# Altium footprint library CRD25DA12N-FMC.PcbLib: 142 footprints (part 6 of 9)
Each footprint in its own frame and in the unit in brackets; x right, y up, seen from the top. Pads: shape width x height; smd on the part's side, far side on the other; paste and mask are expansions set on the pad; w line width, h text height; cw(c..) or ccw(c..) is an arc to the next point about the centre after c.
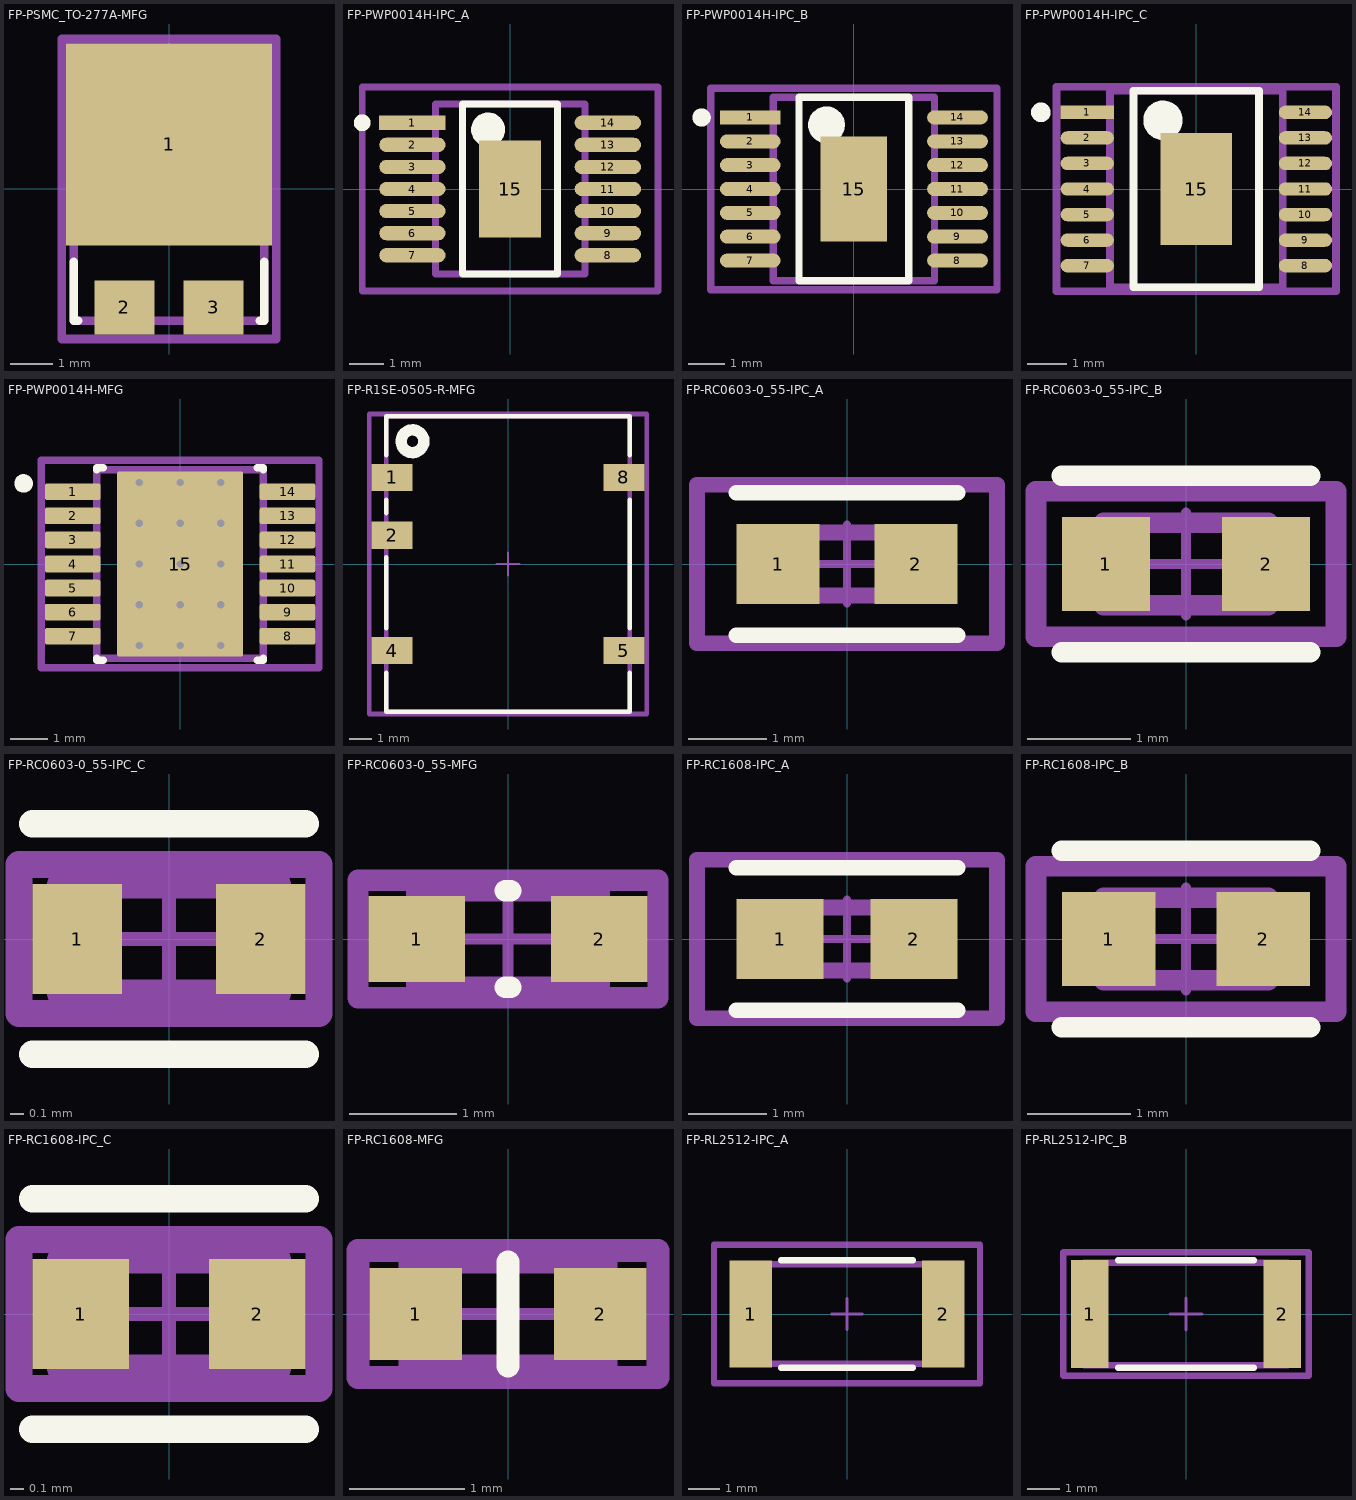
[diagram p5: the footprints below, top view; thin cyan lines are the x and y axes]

## FP-PSMC_TO-277A-MFG [mm]
pads (3):
  rect 4.8x4.72 smd paste+0 mask+0: 1(0,1.04)
  rect 1.4x1.27 smd paste+0 mask+0: 2(-1.04,-2.765) 3(1.04,-2.765)
Top Overlay:
  lines w0.2: -2.225,-1.695 -2.225,-3.075 -2.115,-3.075 ; 2.115,-3.075 2.225,-3.075 2.225,-1.695
Mechanical 5:
  lines w0.2: -2.5,-3.5 -2.5,3.5 2.5,3.5 2.5,-3.5 -2.5,-3.5
  text ".Designator" at 0,0 h1
Mechanical 13:
  lines w0.2: -2.225,-3.075 -2.225,3.075 2.225,3.075 2.225,-3.075 -2.225,-3.075
Mechanical 15:
  lines w0.2: -2.5,-3.5 -2.5,3.5 2.5,3.5 2.5,-3.5 -2.5,-3.5
Mechanical 16:
  lines w0.1: -0.5,0 0.5,0 ; 0,-0.5 0,0.5
3D body "Diode_STMicroelectronics_STPS1045SF_eec.STEP": height 0.25, standoff 0, extent -2.5,-3.5 2.5,3.5

## FP-PWP0014H-IPC_A [mm]
pads (15):
  rect 1.955x0.421 smd paste+0 mask+0: 1(-2.875,1.95)
  rrect100% 1.955x0.421 smd paste+0 mask+0: 2(-2.875,1.3) 3(-2.875,0.65) 4(-2.875,0) 5(-2.875,-0.65) 6(-2.875,-1.3) 7(-2.875,-1.95) 8(2.875,-1.95) 9(2.875,-1.3) 10(2.875,-0.65) 11(2.875,0) 12(2.875,0.65) 13(2.875,1.3) 14(2.875,1.95)
  rect 1.82x2.86 smd paste-1000 mask+0: 15(0,0)
Top Overlay:
  circle w0.25: c-4.353,1.95 r0.125
  circle w0.5: c-0.648,1.75 r0.25
  lines w0.2: -1.398,-2.5 -1.398,2.5 1.398,2.5 1.398,-2.5 -1.398,-2.5
Top Paste:
  rectangle: -0.507,-1.027 0.507,1.027
Mechanical 5:
  lines w0.2: -4.353,-3 -4.353,3 4.353,3 4.353,-3 -4.353,-3
  text ".Designator" at 0,0.188 h1
Mechanical 13:
  lines w0.2: -2.2,-2.5 -2.2,2.5 2.2,2.5 2.2,-2.5 -2.2,-2.5
Mechanical 15:
  lines w0.2: -4.353,-3 -4.353,3 4.353,3 4.353,-3 -4.353,-3
Mechanical 16:
  lines w0.1: -0.5,0 0.5,0 ; 0,-0.5 0,0.5
3D body "IC_Texas_Instruments_ALM2402FQPWPRQ1_eec.STEP": height 0.25, standoff 0, extent -4.353,-3 4.353,3

## FP-PWP0014H-IPC_B [mm]
pads (15):
  rect 1.655x0.381 smd paste+0 mask+0: 1(-2.825,1.95)
  rrect100% 1.655x0.381 smd paste+0 mask+0: 2(-2.825,1.3) 3(-2.825,0.65) 4(-2.825,0) 5(-2.825,-0.65) 6(-2.825,-1.3) 7(-2.825,-1.95) 8(2.825,-1.95) 9(2.825,-1.3) 10(2.825,-0.65) 11(2.825,0) 12(2.825,0.65) 13(2.825,1.3) 14(2.825,1.95)
  rect 1.82x2.86 smd paste-1000 mask+0: 15(0,0)
Top Overlay:
  circle w0.5: c-0.748,1.75 r0.25
  circle w0.25: c-4.153,1.95 r0.125
  lines w0.2: -1.498,-2.5 1.498,-2.5 1.498,2.5 -1.498,2.5 -1.498,-2.5
Top Paste:
  rectangle: -0.507,-1.027 0.507,1.027
Mechanical 5:
  lines w0.2: -3.903,-2.75 3.903,-2.75 3.903,2.75 -3.903,2.75 -3.903,-2.75
  text ".Designator" at 0,0.188 h1
Mechanical 13:
  lines w0.2: -2.2,-2.5 2.2,-2.5 2.2,2.5 -2.2,2.5 -2.2,-2.5
Mechanical 15:
  lines w0.2: -3.903,-2.75 3.903,-2.75 3.903,2.75 -3.903,2.75 -3.903,-2.75
Mechanical 16:
  lines w0.1: -0.5,0 0.5,0 ; 0,-0.5 0,0.5
3D body "IC_Texas_Instruments_ALM2402FQPWPRQ1_eec.STEP": height 0.25, standoff 0, extent -3.903,-2.75 3.903,2.75

## FP-PWP0014H-IPC_C [mm]
pads (15):
  rect 1.355x0.341 smd paste+0 mask+0: 1(-2.775,1.95)
  rrect100% 1.355x0.341 smd paste+0 mask+0: 2(-2.775,1.3) 3(-2.775,0.65) 4(-2.775,0) 5(-2.775,-0.65) 6(-2.775,-1.3) 7(-2.775,-1.95) 8(2.775,-1.95) 9(2.775,-1.3) 10(2.775,-0.65) 11(2.775,0) 12(2.775,0.65) 13(2.775,1.3) 14(2.775,1.95)
  rect 1.82x2.86 smd paste-1000 mask+0: 15(0,0)
Top Overlay:
  circle w0.5: c-0.848,1.75 r0.25
  circle w0.25: c-3.953,1.95 r0.125
  lines w0.2: -1.598,-2.5 1.598,-2.5 1.598,2.5 -1.598,2.5 -1.598,-2.5
Top Paste:
  rectangle: -0.507,-1.027 0.507,1.027
Mechanical 5:
  lines w0.2: -3.553,-2.6 3.553,-2.6 3.553,2.6 -3.553,2.6 -3.553,-2.6
  text ".Designator" at 0,0.188 h1
Mechanical 13:
  lines w0.2: -2.2,-2.5 2.2,-2.5 2.2,2.5 -2.2,2.5 -2.2,-2.5
Mechanical 15:
  lines w0.2: -3.553,-2.6 3.553,-2.6 3.553,2.6 -3.553,2.6 -3.553,-2.6
Mechanical 16:
  lines w0.1: -0.5,0 0.5,0 ; 0,-0.5 0,0.5
3D body "IC_Texas_Instruments_ALM2402FQPWPRQ1_eec.STEP": height 0.25, standoff 0, extent -3.553,-2.6 3.553,2.6

## FP-PWP0014H-MFG [mm]
pads (15):
  rrect22% 1.5x0.45 smd paste+0 mask+0: 1(-2.9,1.95) 2(-2.9,1.3) 3(-2.9,0.65) 4(-2.9,0) 5(-2.9,-0.65) 6(-2.9,-1.3) 7(-2.9,-1.95) 8(2.9,-1.95) 9(2.9,-1.3) 10(2.9,-0.65) 11(2.9,0) 12(2.9,0.65) 13(2.9,1.3) 14(2.9,1.95)
  rrect3% 3.4x5 smd paste-1000 mask-1000: 15(0,0)
via 1.1,2.2 diameter 0.5 hole 0.2
via 1.1,1.1 diameter 0.5 hole 0.2
via 1.1,0 diameter 0.5 hole 0.2
via 1.1,-1.1 diameter 0.5 hole 0.2
via 1.1,-2.2 diameter 0.5 hole 0.2
via -1.1,2.2 diameter 0.5 hole 0.2
via -1.1,1.1 diameter 0.5 hole 0.2
via -1.1,0 diameter 0.5 hole 0.2
via -1.1,-1.1 diameter 0.5 hole 0.2
via -1.1,-2.2 diameter 0.5 hole 0.2
via 0,2.2 diameter 0.5 hole 0.2
via 0,1.1 diameter 0.5 hole 0.2
via 0,0 diameter 0.5 hole 0.2
via 0,-1.1 diameter 0.5 hole 0.2
via 0,-2.2 diameter 0.5 hole 0.2
Top Overlay:
  circle w0.25: c-4.225,2.175 r0.125
  lines w0.2: -2.25,-2.55 -2.25,-2.6 -2.075,-2.6 ; -2.25,2.55 -2.25,2.6 -2.075,2.6 ; 2.075,-2.6 2.25,-2.6 2.25,-2.55 ; 2.075,2.6 2.25,2.6 2.25,2.55
Top Paste:
  region: 0.91,1.38 0.91,-1.38 0.91,-1.39 0.902,-1.408 0.888,-1.422 0.87,-1.43 0.86,-1.43 -0.86,-1.43 -0.87,-1.43 -0.888,-1.422 -0.902,-1.408 -0.91,-1.39 -0.91,-1.38 -0.91,1.38 -0.91,1.39 -0.902,1.408 -0.888,1.422 -0.87,1.43 -0.86,1.43 0.86,1.43 0.87,1.43 0.888,1.422 0.902,1.408 0.91,1.39
Top Solder:
  region: 0.91,1.38 0.91,-1.38 0.91,-1.39 0.902,-1.408 0.888,-1.422 0.87,-1.43 0.86,-1.43 -0.86,-1.43 -0.87,-1.43 -0.888,-1.422 -0.902,-1.408 -0.91,-1.39 -0.91,-1.38 -0.91,1.38 -0.91,1.39 -0.902,1.408 -0.888,1.422 -0.87,1.43 -0.86,1.43 0.86,1.43 0.87,1.43 0.888,1.422 0.902,1.408 0.91,1.39
Mechanical 5:
  lines w0.2: -3.75,-2.8 3.75,-2.8 3.75,2.8 -3.75,2.8 -3.75,-2.8
  text ".Designator" at 0,0.188 h1
Mechanical 13:
  lines w0.2: -2.25,-2.55 2.25,-2.55 2.25,2.55 -2.25,2.55 -2.25,-2.55
Mechanical 15:
  lines w0.2: -3.75,-2.8 3.75,-2.8 3.75,2.8 -3.75,2.8 -3.75,-2.8
Mechanical 16:
  lines w0.1: -0.5,0 0.5,0 ; 0,-0.5 0,0.5
3D body "IC_Texas_Instruments_ALM2402FQPWPRQ1_eec.STEP": height 0.25, standoff 0, extent -3.75,-2.8 3.75,2.8

## FP-R1SE-0505-R-MFG [mm]
pads (5):
  rect 1.8x1.2 smd paste+0 mask+0: 1(-5.1,3.81) 2(-5.1,1.27) 4(-5.1,-3.81) 5(5.1,-3.81) 8(5.1,3.81)
Top Overlay:
  circle w0.5: c-4.2,5.4 r0.5
  lines w0.2: -5.35,-4.785 -5.35,-6.5 5.35,-6.5 5.35,-4.785 ; -5.35,-2.835 -5.35,0.295 ; -5.35,2.245 -5.35,2.835 ; -5.35,4.785 -5.35,6.5 5.35,6.5 5.35,4.785 ; 5.35,-2.835 5.35,2.835
Mechanical 5:
  lines w0.2: -6.1,-6.6 6.1,-6.6 6.1,6.6 -6.1,6.6 -6.1,-6.6
  text ".Designator" at 0,0.188 h1
Mechanical 13:
  lines w0.2: -5.35,-6.5 5.35,-6.5 5.35,6.5 -5.35,6.5 -5.35,-6.5
Mechanical 15:
  lines w0.2: -6.1,-6.6 6.1,-6.6 6.1,6.6 -6.1,6.6 -6.1,-6.6
Mechanical 16:
  lines w0.1: -0.5,0 0.5,0 ; 0,-0.5 0,0.5
3D body "IC_Recom_Power_R1SE-0505-R_eec.STEP": height 0.25, standoff 0, extent -6.1,-6.6 6.1,6.6

## FP-RC0603-0_55-IPC_A [mm]
pads (2):
  rect 1.059x1.012 smd paste+0 mask+0: 1(-0.877,0) 2(0.877,0)
Top Overlay:
  lines w0.2: -1.406,-0.906 1.406,-0.906 ; -1.406,0.906 1.406,0.906
Mechanical 5:
  lines w0.2: -1.906,-1.006 1.906,-1.006 1.906,1.006 -1.906,1.006 -1.906,-1.006
  text ".Designator" at 0,0.188 h1
Mechanical 13:
  lines w0.2: -0.8,-0.4 0.8,-0.4 0.8,0.4 -0.8,0.4 -0.8,-0.4
Mechanical 15:
  lines w0.2: -1.906,-1.006 1.906,-1.006 1.906,1.006 -1.906,1.006 -1.906,-1.006
Mechanical 16:
  lines w0.1: -0.5,0 0.5,0 ; 0,-0.5 0,0.5
3D body "Res_Yageo_RC0603FR-07100KL_eec.STEP": height 0.25, standoff 0, extent -1.906,-1.006 1.906,1.006

## FP-RC0603-0_55-IPC_B [mm]
pads (2):
  rect 0.859x0.912 smd paste+0 mask+0: 1(-0.777,0) 2(0.777,0)
Top Overlay:
  lines w0.2: -1.206,-0.856 1.206,-0.856 ; -1.206,0.856 1.206,0.856
Mechanical 5:
  lines w0.2: -1.456,-0.706 1.456,-0.706 1.456,0.706 -1.456,0.706 -1.456,-0.706
  text ".Designator" at 0,0.188 h1
Mechanical 13:
  lines w0.2: -0.8,-0.4 0.8,-0.4 0.8,0.4 -0.8,0.4 -0.8,-0.4
Mechanical 15:
  lines w0.2: -1.456,-0.706 1.456,-0.706 1.456,0.706 -1.456,0.706 -1.456,-0.706
Mechanical 16:
  lines w0.1: -0.5,0 0.5,0 ; 0,-0.5 0,0.5
3D body "Res_Yageo_RC0603FR-07100KL_eec.STEP": height 0.25, standoff 0, extent -1.456,-0.706 1.456,0.706

## FP-RC0603-0_55-IPC_C [mm]
pads (2):
  rect 0.659x0.812 smd paste+0 mask+0: 1(-0.677,0) 2(0.677,0)
Top Overlay:
  lines w0.2: -1.006,-0.85 1.006,-0.85 ; -1.006,0.85 1.006,0.85
Mechanical 5:
  lines w0.2: -1.106,-0.55 -1.106,0.55 1.106,0.55 1.106,-0.55 -1.106,-0.55
  text ".Designator" at 0,0.188 h1
Mechanical 13:
  lines w0.2: -0.8,-0.4 -0.8,0.4 0.8,0.4 0.8,-0.4 -0.8,-0.4
Mechanical 15:
  lines w0.2: -1.106,-0.55 -1.106,0.55 1.106,0.55 1.106,-0.55 -1.106,-0.55
Mechanical 16:
  lines w0.1: -0.5,0 0.5,0 ; 0,-0.5 0,0.5
3D body "Res_Yageo_RC0603FR-07100KL_eec.STEP": height 0.25, standoff 0, extent -1.106,-0.55 1.106,0.55

## FP-RC0603-0_55-MFG [mm]
pads (2):
  rect 0.9x0.8 smd paste+0 mask+0: 1(-0.85,0) 2(0.85,0)
Top Overlay:
  lines w0.2: -0.025,-0.45 0.025,-0.45 ; -0.025,0.45 0.025,0.45
Mechanical 5:
  lines w0.2: -1.4,-0.55 1.4,-0.55 1.4,0.55 -1.4,0.55 -1.4,-0.55
  text ".Designator" at 0,0.188 h1
Mechanical 13:
  lines w0.2: -0.85,-0.45 0.85,-0.45 0.85,0.45 -0.85,0.45 -0.85,-0.45
Mechanical 15:
  lines w0.2: -1.4,-0.55 1.4,-0.55 1.4,0.55 -1.4,0.55 -1.4,-0.55
Mechanical 16:
  lines w0.1: -0.5,0 0.5,0 ; 0,-0.5 0,0.5
3D body "Res_Yageo_RC0603FR-07100KL_eec.STEP": height 0.25, standoff 0, extent -1.4,-0.55 1.4,0.55

## FP-RC1608-IPC_A [mm]
pads (2):
  rect 1.11x1.012 smd paste+0 mask+0: 1(-0.851,0) 2(0.851,0)
Top Overlay:
  lines w0.2: -1.406,-0.906 1.406,-0.906 ; -1.406,0.906 1.406,0.906
Mechanical 5:
  lines w0.2: -1.906,-1.006 1.906,-1.006 1.906,1.006 -1.906,1.006 -1.906,-1.006
  text ".Designator" at 0,0.188 h1
Mechanical 13:
  lines w0.2: -0.8,-0.4 0.8,-0.4 0.8,0.4 -0.8,0.4 -0.8,-0.4
Mechanical 15:
  lines w0.2: -1.906,-1.006 1.906,-1.006 1.906,1.006 -1.906,1.006 -1.906,-1.006
Mechanical 16:
  lines w0.1: -0.5,0 0.5,0 ; 0,-0.5 0,0.5
3D body "Res_Samsung_RC1608F7873CS_eec.STEP": height 0.25, standoff 0, extent -1.906,-1.006 1.906,1.006

## FP-RC1608-IPC_B [mm]
pads (2):
  rect 0.91x0.912 smd paste+0 mask+0: 1(-0.751,0) 2(0.751,0)
Top Overlay:
  lines w0.2: -1.206,-0.856 1.206,-0.856 ; -1.206,0.856 1.206,0.856
Mechanical 5:
  lines w0.2: -1.456,-0.706 1.456,-0.706 1.456,0.706 -1.456,0.706 -1.456,-0.706
  text ".Designator" at 0,0.188 h1
Mechanical 13:
  lines w0.2: -0.8,-0.4 0.8,-0.4 0.8,0.4 -0.8,0.4 -0.8,-0.4
Mechanical 15:
  lines w0.2: -1.456,-0.706 1.456,-0.706 1.456,0.706 -1.456,0.706 -1.456,-0.706
Mechanical 16:
  lines w0.1: -0.5,0 0.5,0 ; 0,-0.5 0,0.5
3D body "Res_Samsung_RC1608F7873CS_eec.STEP": height 0.25, standoff 0, extent -1.456,-0.706 1.456,0.706

## FP-RC1608-IPC_C [mm]
pads (2):
  rect 0.71x0.812 smd paste+0 mask+0: 1(-0.651,0) 2(0.651,0)
Top Overlay:
  lines w0.2: -1.006,-0.85 1.006,-0.85 ; -1.006,0.85 1.006,0.85
Mechanical 5:
  lines w0.2: -1.106,-0.55 1.106,-0.55 1.106,0.55 -1.106,0.55 -1.106,-0.55
  text ".Designator" at 0,0.188 h1
Mechanical 13:
  lines w0.2: -0.8,-0.4 0.8,-0.4 0.8,0.4 -0.8,0.4 -0.8,-0.4
Mechanical 15:
  lines w0.2: -1.106,-0.55 1.106,-0.55 1.106,0.55 -1.106,0.55 -1.106,-0.55
Mechanical 16:
  lines w0.1: -0.5,0 0.5,0 ; 0,-0.5 0,0.5
3D body "Res_Samsung_RC1608F7873CS_eec.STEP": height 0.25, standoff 0, extent -1.106,-0.55 1.106,0.55

## FP-RC1608-MFG [mm]
pads (2):
  rect 0.8x0.8 smd paste+0 mask+0: 1(-0.8,0) 2(0.8,0)
Top Overlay:
  lines w0.2: 0,-0.45 0,0.45
Mechanical 5:
  lines w0.2: -1.3,-0.55 1.3,-0.55 1.3,0.55 -1.3,0.55 -1.3,-0.55
  text ".Designator" at 0,0 h1
Mechanical 13:
  lines w0.2: -0.85,-0.45 0.85,-0.45 0.85,0.45 -0.85,0.45 -0.85,-0.45
Mechanical 15:
  lines w0.2: -1.3,-0.55 1.3,-0.55 1.3,0.55 -1.3,0.55 -1.3,-0.55
Mechanical 16:
  lines w0.1: -0.5,0 0.5,0 ; 0,-0.5 0,0.5
3D body "Res_Samsung_RC1608F7873CS_eec.STEP": height 0.25, standoff 0, extent -1.3,-0.55 1.3,0.55

## FP-RL2512-IPC_A [mm]
pads (2):
  rect 1.358x3.458 smd paste+0 mask+0: 1(-3.102,0) 2(3.102,0)
Top Overlay:
  lines w0.2: -2.123,-1.729 2.123,-1.729 ; -2.123,1.729 2.123,1.729
Mechanical 5:
  lines w0.2: -4.281,-2.229 -4.281,2.229 4.281,2.229 4.281,-2.229 -4.281,-2.229
  text ".Designator" at 0,0.188 h1
Mechanical 13:
  lines w0.2: -3.175,-1.6 -3.175,1.6 3.175,1.6 3.175,-1.6 -3.175,-1.6
Mechanical 15:
  lines w0.2: -4.281,-2.229 -4.281,2.229 4.281,2.229 4.281,-2.229 -4.281,-2.229
Mechanical 16:
  lines w0.1: -0.5,0 0.5,0 ; 0,-0.5 0,0.5
3D body "Res_YAGEO_RL2512FK-070R1L_eec.STEP": height 0.25, standoff 0, extent -4.281,-2.229 4.281,2.229

## FP-RL2512-IPC_B [mm]
pads (2):
  rect 1.158x3.358 smd paste+0 mask+0: 1(-3.002,0) 2(3.002,0)
Top Overlay:
  lines w0.2: -2.123,-1.679 2.123,-1.679 ; -2.123,1.679 2.123,1.679
Mechanical 5:
  lines w0.2: -3.831,-1.929 -3.831,1.929 3.831,1.929 3.831,-1.929 -3.831,-1.929
  text ".Designator" at 0,0.188 h1
Mechanical 13:
  lines w0.2: -3.175,-1.6 -3.175,1.6 3.175,1.6 3.175,-1.6 -3.175,-1.6
Mechanical 15:
  lines w0.2: -3.831,-1.929 -3.831,1.929 3.831,1.929 3.831,-1.929 -3.831,-1.929
Mechanical 16:
  lines w0.1: -0.5,0 0.5,0 ; 0,-0.5 0,0.5
3D body "Res_YAGEO_RL2512FK-070R1L_eec.STEP": height 0.25, standoff 0, extent -3.831,-1.929 3.831,1.929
